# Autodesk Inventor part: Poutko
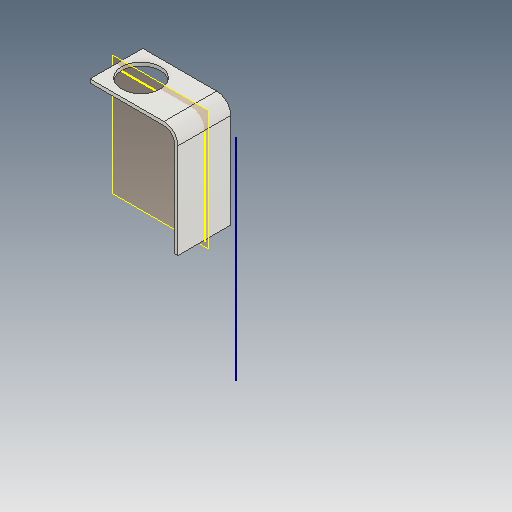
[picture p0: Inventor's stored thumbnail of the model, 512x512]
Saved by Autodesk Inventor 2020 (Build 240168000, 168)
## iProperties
Created: 2025-04
Part Number: Poutko
Material: Ocel
Document SubType Name: Modeling
Designer: doma
Density: 7.85 g/cm^3
Appearance: Ocel
Mass: 5.55335 g
Surface Area: 15.8642 cm^2
Volume: 0.707434 cm^3
Author: doma
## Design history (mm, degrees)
sketch "Náčrt1"
  geometry: L1 (0, 0)-(21, 0); L2 (24, -3)-(24, -30); L3 (0, 1)-(21, 1); L4 (25, -3)-(25, -30); L5 (0, 1)-(0, 0); L6 (25, -30)-(24, -30); A1 r 3 centre (21, -3) between (24, -3) and (21, 0); A2 r 4 centre (21, -3) between (25, -3) and (21, 1); 1 further point
  constraints: 12 end point, 4 point on circle, 2 centre point, 2 horizontal, 2 point on line, 2 tangent, 2 vertical, 2 other
  dimensions: "d0" = 24 distance of L1.start point (24, 0); "d1" = 30 distance of point (24, 0) L2.end; "d2" = 3 radius of A1; "d3" = 1 distance between parallel lines of L1 L3
extrude "Vysunutí1" new body sketch "Náčrt1" distance "d4" = 15; taper "d5" = 0 deg
sketch "Náčrt2"
  geometry: L1 (0, 0)-(0, -15) reference; L2 (0, -7.5)-(7, -7.5); C1 r 5.5 at (7, -7.5)
  constraints: 2 end point, 1 centre point, 1 coincident, 1 horizontal, 1 midpoint
  dimensions: "d6" = 7 distance of L2.start L2.end; "d7" = 11 diameter of C1
extrude "Vysunutí2" cut sketch "Náčrt2" distance "d8" = 15; taper "d9" = 0 deg
node "Pracovní rovina1"
sketch "Náčrt3"
  geometry: L1 (34, 0)-(34, -60); L2 (25, -30)-(25, -3) reference; L3 (0, 0)-(21, 0) reference
  constraints: 2 end point, 1 point on line, 1 vertical
  dimensions: "d10" = 9 distance between parallel lines of L2 L1; "d11" = 60 distance of L1.start L1.end
node "Těleso1"
